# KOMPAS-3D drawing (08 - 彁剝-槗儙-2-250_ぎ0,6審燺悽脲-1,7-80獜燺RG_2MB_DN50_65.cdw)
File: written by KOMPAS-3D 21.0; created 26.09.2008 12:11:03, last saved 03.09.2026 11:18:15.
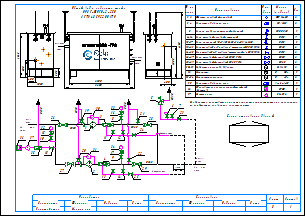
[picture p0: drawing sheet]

Sheets 1-2: A3, landscape

Document properties: Наименование: Макро:21; Автор: RaskoAdmin; Форматы листов документа: 2xA3; Полное имя файла: \\UR38nt01\Departments\КТО\КБ ПУРДГ\Заявки\Прайс-лист на типовые шкафы ГРПШ\ПРДГ_стандарт_20_03_2026\ПРДГ с RG_2MB\ПРДГ-ШУГО-2-250_до0,6МПа_Рвых-1,7-80кПа_RG_2MB_DN50_65.cdw

Title block, sheet 1: Наименование: Пункт учета газа / ПУГ-Ш-400-Р / ЛГТИ.485922.001ТУ; designation: ЛГТИ.03.4411141; sheet number: 1; Количество листов документа: 2; organisation: ООО "ЭЛЬСТЕР Газэлектроника"; Форматы листов документа: A3; stored path: C:\Рабочие документы\Компас\ПУГ\Схема.cdw; Разработал: Устинов; Проверил: Кошкин; Утвердил: Кошкин
Title block, sheet 2: sheet number: 2; stored path: D:\Рабочие документы\Заявки\ПУРДГ\ПУРДГ-ШУЭО-2-100-Р 4411220.cdw; designation, second copy: ЛГТИ.03.4411141-

Views: Вид 1, Вид 2
Referenced files: wcvoit.frw
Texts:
  Normal
  Вход
  газа
  PDI
  Выход
  Р=     кПа
  DN65
  DN50
  DN20
  Импульс DN20
  ≥5DN
  HYSWLongFangSong
  Общий вид и габариты шкафа
  ПРДГ-ШУГО-2-250
  Выход газа
  Вход газа
  Р=        МПа
  logo-rasko-ge.png
  № на
  схеме
  Усл.
  обозн.
  Марка
  (модель)
  Кол.
  Фильтр газовый фланцевый
  ФГ 16-50
  Регулятор давления газа
  RG/2MB
  Клапан предохранительный сбросной
  КПС DN20
  Кран шаровой газовый латунный
  DN15
  Кран кнопочный VE-РАСКО-НЗ-1,6-G1/2-М20
  Кран шаровой "под приварку" штуцерный DN20 PN16
  Кран шаровой "под приварку" штуцерный п/п DN15 PN16
  Кран шаровой фланцевый DN50 PN16
  Кран шаровой фланцевый DN65 PN16
  Индикатор перепада давления
  Delta 15
  Манометр
  Манометр-напоромер
  0...     МПа
  0...     кПа
  Обогреватель газогорелочный шкафной
  (Эльтон")
  Счетчик газа
  Venio-A-15
  ОГШН
  BK-G1,6
  Схема открывания дверей
  Предприятие изготовитель может заменять комплектующие на аналогичные,
  не ухудшающие заявленных характеристик.
  Должность
  Конструктор
  Фамилия
  Подпись
  Дата
  Согласовано
  Максимкин
  Лист
  Листов
  POLYLINE_STYLE_0.18_RGB_0_0_0
  POLYLINE_STYLE_0.50_RGB_0_0_0
  POLYLINE_STYLE_0.34_RGB_0_0_0
  PHANTOM_RGB_0_0_0_SC_1_THICK_0.18
  K5LT_THIN_RGB_0_0_0_THICK_0.18
  K5LT32769_RGB_0_0_0_THICK_0.18
  K5LT12_RGB_0_0_0_SC_1_THICK_0.18
  K5LT_DASHED_RGB_0_0_0_SC_1_THICK_0.18
  ACISOTGL_RGB_0_0_0_SC_0.8_THICK_0.25
  CONTINUOUS_RGB_0_127_31_THICK_0.3
  CONTINUOUS_RGB_0_0_255_THICK_0.35
  CONTINUOUS_RGB_255_0_0_THICK_0.35
  POLYLINE_STYLE_0.25_RGB_0_0_0
  CONTINUOUS_RGB_0_0_0_THICK_0.5
  POLYLINE_STYLE_0.35_RGB_0_0_255
  CONTINUOUS_RGB_0_0_0_THICK_0.4
  CONTINUOUS_RGB_0_0_0_THICK_0.35
  Без оформления
Dimensions and other numbers on the sheet: 1; 2; 3; 4; 5; 10; 27; 28; 29; 23; 8; 12; 19; 20; 21; 22; 25; 24; 30; 31; 15; 16; 26; 6; 7; 11; 14; 13; 33; 400; 1050; 500; 305; 2300; 1565; 32; 2600; 9; 17; 34; 1000; 4130; 1, 2; 3, 4; 6-14; 15-17; 18-23; 24-25; 26-27; 28-29; 30-31; 33-34; 35; 36; 37; 18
